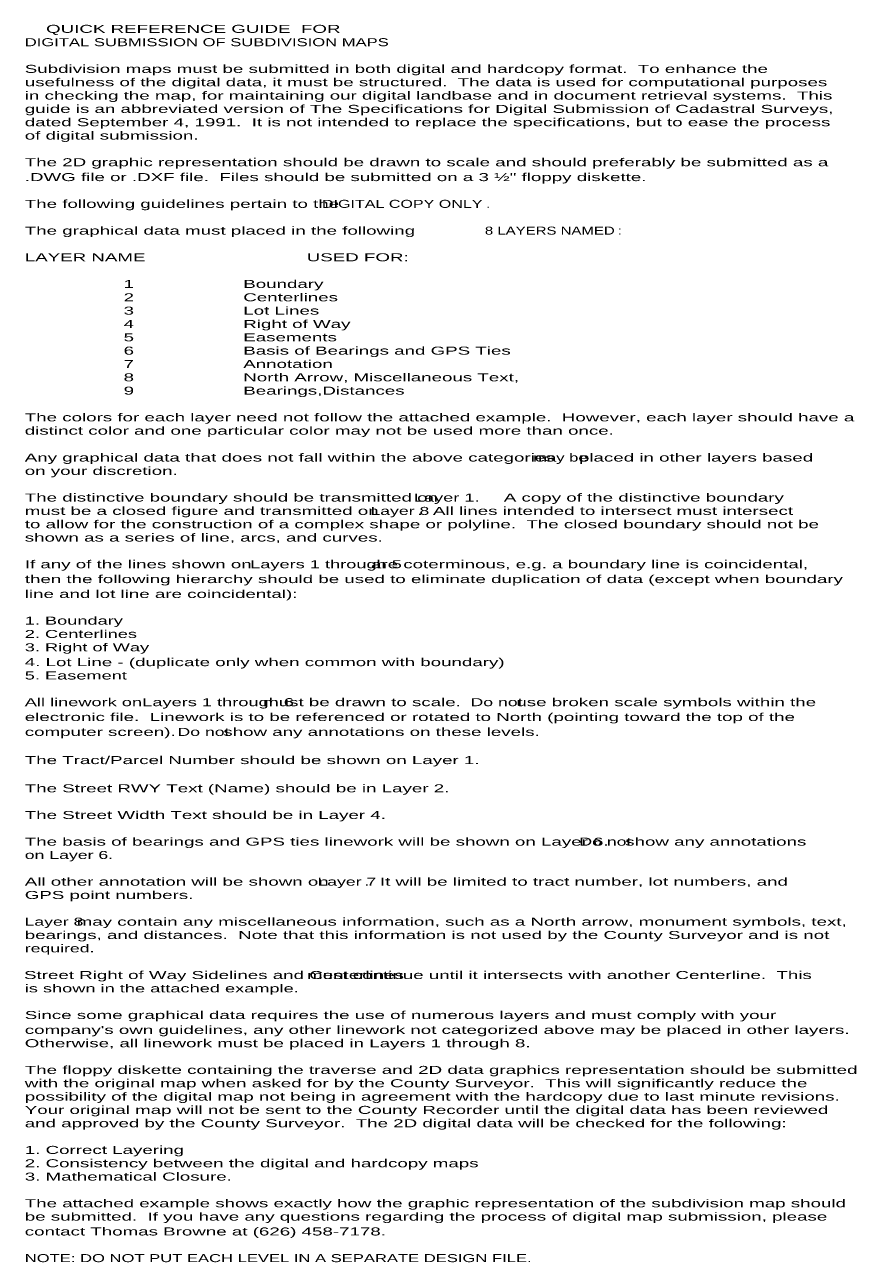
# Model space of a CAD drawing. Extents: x 6387474 to 6390971, y 1972046 to 1973920.
# Drawn here: x 6387474 to 6388513, y 1972191 to 1973737 of the extents above; entities that cross this region are included whole.
import ezdxf

# ---------------------------------------------------------------- set-up
doc = ezdxf.new("R2010")
doc.units = 0
doc.header["$LTSCALE"] = 4
doc.layers.add('9', color=7, linetype='Continuous')

msp = doc.modelspace()

# ---------------------------------------------------------------- texts
at = {"layer": '9'}
for s, width, p in [('QUICK REFERENCE GUIDE  FOR                                                                  ', 1.75, (6387500.604, 1973727.071)), ('DIGITAL SUBMISSION OF SUBDIVISION MAPS', 1.55, (6387473.968, 1973710.404)), ('Subdivision maps must be submitted in both digital and hardcopy format.  To enhance the ', 1.75, (6387473.968, 1973677.071)), ('usefulness of the digital data, it must be structured.  The data is used for computational purposes ', 1.75, (6387473.968, 1973660.404)), ('in checking the map, for maintaining our digital landbase and in document retrieval systems.  This ', 1.75, (6387473.968, 1973643.737)), ('guide is an abbreviated version of The Specifications for Digital Submission of Cadastral Surveys, ', 1.75, (6387473.968, 1973627.071)), ('dated September 4, 1991.  It is not intended to replace the specifications, but to ease the process ', 1.75, (6387473.968, 1973610.404)), ('of digital submission.  ', 1.75, (6387473.968, 1973593.737)), ('The 2D graphic representation should be drawn to scale and should preferably be submitted as a ', 1.75, (6387473.968, 1973560.404)), ('.DWG file or .DXF file.  Files should be submitted on a 3 ½" floppy diskette.  ', 1.75, (6387473.968, 1973541.833)), ('The following guidelines pertain to the ', 1.75, (6387473.968, 1973508.391)), ('DIGITAL COPY ONLY', 1.5, (6387845.397, 1973508.391)), ('The graphical data must placed in the following ', 1.75, (6387473.968, 1973474.949)), ('8 LAYERS NAMED', 1.4, (6388048.987, 1973474.949)), ('LAYER NAME                               USED FOR:', 1.75, (6387473.968, 1973441.616)), ('                   1                     Boundary', 1.75, (6387473.968, 1973408.282)), ('                   2                     Centerlines', 1.75, (6387473.968, 1973391.616)), ('                   3                     Lot Lines', 1.75, (6387473.968, 1973374.949)), ('                   4                     Right of Way', 1.75, (6387473.968, 1973358.282)), ('                   5                     Easements', 1.75, (6387473.968, 1973341.616)), ('                   6                     Basis of Bearings and GPS Ties', 1.75, (6387473.968, 1973324.949)), ('                   7                     Annotation', 1.75, (6387473.968, 1973308.282)), ('                   8                     North Arrow, Miscellaneous Text,  ', 1.75, (6387473.968, 1973291.616)), ('                   9                     Bearings,Distances', 1.75, (6387473.968, 1973274.949)), ('The colors for each layer need not follow the attached example.  However, each layer should have a ', 1.75, (6387473.968, 1973241.616)), ('distinct color and one particular color may not be used more than once.', 1.75, (6387473.968, 1973224.949)), ('Any graphical data that does not fall within the above categories ', 1.75, (6387473.968, 1973191.363)), ('may be', 1.55, (6388109.397, 1973191.363)), (' placed in other layers based ', 1.75, (6388160.07, 1973191.363)), ('on your discretion.  ', 1.75, (6387473.968, 1973174.697)), ('The distinctive boundary should be transmitted on ', 1.75, (6387473.968, 1973141.363)), ('Layer 1. ', 1.7, (6387960.254, 1973141.363)), ('A copy of the distinctive boundary ', 1.75, (6388072.693, 1973141.363)), ('must be a closed figure and transmitted on ', 1.75, (6387473.968, 1973124.697)), ('Layer 8', 1.65, (6387905.968, 1973124.697)), ('.  All lines intended to intersect must intersect ', 1.75, (6387964.65, 1973124.697)), ('to allow for the construction of a complex shape or polyline.  The closed boundary should not be ', 1.75, (6387473.968, 1973108.03)), ('shown as a series of line, arcs, and curves.', 1.75, (6387473.968, 1973091.363)), ('If any of the lines shown on ', 1.75, (6387473.968, 1973058.03)), ('Layers 1 through 5', 1.7, (6387755.682, 1973058.03)), (' are coterminous, e.g. a boundary line is coincidental, ', 1.75, (6387900.211, 1973058.03)), ('then the following hierarchy should be used to eliminate duplication of data (except when boundary ', 1.75, (6387473.968, 1973039.459)), ('line and lot line are coincidental):', 1.75, (6387473.968, 1973020.887)), ('1. Boundary', 1.7, (6387473.968, 1972987.554)), ('2. Centerlines', 1.7, (6387473.968, 1972970.887)), ('3. Right of Way', 1.7, (6387473.968, 1972954.221)), ('4. Lot Line - (duplicate only when common with boundary)', 1.75, (6387473.968, 1972935.649)), ('5. Easement', 1.7, (6387473.968, 1972918.982)), ('All linework on ', 1.7, (6387473.968, 1972885.649)), ('Layers 1 through 6', 1.7, (6387620.825, 1972885.649)), (' must be drawn to scale.  ', 1.75, (6387765.354, 1972885.649)), ('Do not', 1.65, (6388031.068, 1972885.649)), (' use broken scale symbols within the ', 1.75, (6388081.878, 1972885.649)), ('electronic file.  Linework is to be referenced or rotated to North (pointing toward the top of the ', 1.75, (6387473.968, 1972867.078)), ('computer screen).  ', 1.75, (6387473.968, 1972848.506)), ('Do not', 1.65, (6387664.825, 1972848.506)), (' show any annotations on these levels.', 1.75, (6387715.634, 1972848.506)), ('The Tract/Parcel Number should be shown on Layer 1.', 1.75, (6387473.968, 1972813.268)), ('The Street RWY Text (Name) should be in Layer 2.', 1.75, (6387473.968, 1972778.03)), ('The Street Width Text should be in Layer 4.', 1.75, (6387473.968, 1972744.697)), ('The basis of bearings and GPS ties linework will be shown on Layer 6.  ', 1.75, (6387473.968, 1972711.363)), ('Do not', 1.65, (6388167.111, 1972711.363)), (' show any annotations ', 1.75, (6388217.92, 1972711.363)), ('on Layer 6.', 1.65, (6387473.968, 1972694.697)), ('All other annotation will be shown on ', 1.75, (6387473.968, 1972661.363)), ('Layer 7', 1.65, (6387839.682, 1972661.363)), ('.  It will be limited to tract number, lot numbers, and ', 1.75, (6387898.364, 1972661.363)), ('GPS point numbers.  ', 1.75, (6387473.968, 1972644.697)), ('Layer 8', 1.65, (6387473.639, 1972611.363)), (' may contain any miscellaneous information, such as a North arrow, monument symbols, text, ', 1.75, (6387532.321, 1972611.363)), ('bearings, and distances.  Note that this information is not used by the County Surveyor and is not ', 1.75, (6387473.968, 1972594.697)), ('required.', 1.65, (6387473.968, 1972578.03)), ('Street Right of Way Sidelines and Centerlines', 1.75, (6387473.049, 1972544.668)), (' must continue until it intersects with another Centerline.  This ', 1.75, (6387820.286, 1972544.668)), ('is shown in the attached example.', 1.7, (6387473.968, 1972528.001)), ('Since some graphical data requires the use of numerous layers and must comply with your ', 1.75, (6387473.968, 1972494.668)), ("company's own guidelines, any other linework not categorized above may be placed in other layers.  ", 1.75, (6387473.968, 1972476.096)), ('Otherwise, all linework must be placed in Layers 1 through 8.', 1.75, (6387473.968, 1972459.43)), ('The floppy diskette containing the traverse and 2D data graphics representation should be submitted ', 1.75, (6387473.968, 1972426.096)), ('with the original map when asked for by the County Surveyor.  This will significantly reduce the ', 1.75, (6387473.968, 1972409.43)), ('possibility of the digital map not being in agreement with the hardcopy due to last minute revisions.  ', 1.75, (6387473.968, 1972392.763)), ('Your original map will not be sent to the County Recorder until the digital data has been reviewed ', 1.75, (6387473.968, 1972376.096)), ('and approved by the County Surveyor.  The 2D digital data will be checked for the following:', 1.75, (6387473.968, 1972359.43)), ('1. Correct Layering', 1.75, (6387473.968, 1972326.096)), ('2. Consistency between the digital and hardcopy maps', 1.75, (6387473.968, 1972309.43)), ('3. Mathematical Closure.   ', 1.75, (6387473.968, 1972292.763)), ('The attached example shows exactly how the graphic representation of the subdivision map should ', 1.75, (6387473.968, 1972259.43)), ('be submitted.  If you have any questions regarding the process of digital map submission, please ', 1.75, (6387473.968, 1972242.763)), ('contact Thomas Browne at (626) 458-7178.', 1.75, (6387473.968, 1972224.192)), ('NOTE: DO NOT PUT EACH LEVEL IN A SEPARATE DESIGN FILE.', 1.55, (6387473.968, 1972190.858))]:
    msp.add_text(s, height=10, dxfattribs=dict(at, width=width)).set_placement(p)
for s, p in [('.', (6388051.195, 1973508.391)), (':', (6388215.753, 1973474.949))]:
    msp.add_text(s, height=10, dxfattribs=at).set_placement(p)

doc.saveas('drawing.dxf')
